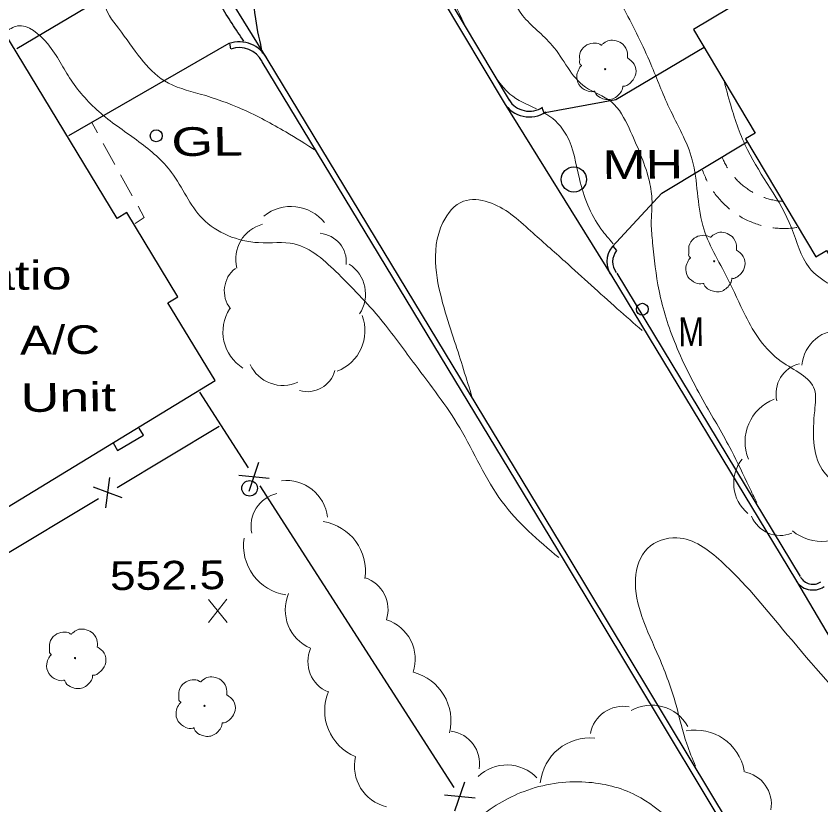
# Model space of a CAD drawing. Extents: x 2361708 to 2370558, y 6977955 to 6991887.
# Drawn here: x 2366412.5 to 2366547.1, y 6982751.7 to 6982883.6 of the extents above; entities that cross this region are included whole.
import ezdxf

# ---------------------------------------------------------------- set-up
doc = ezdxf.new("R2010")
doc.units = 0
doc.header["$LTSCALE"] = 1.9
for name, color, linetype, lineweight in [('11', 7, 'Continuous', 25), ('13', 7, 'Continuous', 13), ('14', 7, 'Continuous', 13), ('17', 7, 'Continuous', 25), ('2', 7, 'Continuous', 25), ('20', 7, 'Continuous', 25), ('23', 7, 'Continuous', 25), ('29', 7, 'Continuous', 13), ('31', 7, 'Continuous', 13), ('35', 7, 'Continuous', 13)]:
    doc.layers.add(name, color=color, linetype=linetype, lineweight=lineweight)

msp = doc.modelspace()

# ---------------------------------------------------------------- linework, layer by layer
at = {"layer": '11'}
for points in [[(2366556.942, 6982829.566), (2366598.547, 6982854.472), (2366579.524, 6982886.263), (2366569.301, 6982880.146), (2366557.3, 6982900.212), (2366525.798, 6982881.361), (2366536.143, 6982864.059), (2366534.502, 6982863.074), (2366546.301, 6982843.335), (2366548.061, 6982844.391)], [(2366404.142, 6982797.319), (2366445.793, 6982822.667), (2366437.889, 6982835.643), (2366439.559, 6982836.659), (2366430.994, 6982850.758), (2366429.374, 6982849.772), (2366410.435, 6982881.013), (2366381.789, 6982863.65), (2366388.231, 6982853.021), (2366387.068, 6982852.32), (2366391.914, 6982844.315), (2366393.087, 6982845.027), (2366403.114, 6982828.581), (2366389.96, 6982820.555)]]:
    msp.add_lwpolyline(points, close=True, dxfattribs=at)
at = {"layer": '13'}
for p, q in [((2366425.141, 6982865.822), (2366426.107, 6982864.072)), ((2366427.074, 6982862.321), (2366429.007, 6982858.819)), ((2366429.974, 6982857.068), (2366431.918, 6982853.567))]:
    msp.add_line(p, q, dxfattribs=at)
for points in [[(2366530.591, 6982860.026), (2366530.673, 6982859.837), (2366530.754, 6982859.648), (2366530.836, 6982859.459), (2366530.928, 6982859.269), (2366531.02, 6982859.08), (2366531.112, 6982858.901), (2366531.213, 6982858.722), (2366531.315, 6982858.543), (2366531.416, 6982858.364), (2366531.488, 6982858.244)], [(2366527.332, 6982857.825), (2366527.414, 6982857.586), (2366527.506, 6982857.357), (2366527.598, 6982857.118), (2366527.691, 6982856.888), (2366527.793, 6982856.649), (2366527.895, 6982856.42), (2366528.007, 6982856.201), (2366528.109, 6982855.982)], [(2366532.673, 6982856.636), (2366532.764, 6982856.537), (2366532.906, 6982856.378), (2366533.047, 6982856.229), (2366533.189, 6982856.081), (2366533.33, 6982855.942), (2366533.481, 6982855.794), (2366533.633, 6982855.655), (2366533.794, 6982855.516), (2366533.945, 6982855.387), (2366534.106, 6982855.249), (2366534.268, 6982855.121), (2366534.429, 6982854.992), (2366534.6, 6982854.874), (2366534.771, 6982854.756), (2366534.942, 6982854.637), (2366535.114, 6982854.519), (2366535.284, 6982854.41), (2366535.456, 6982854.302), (2366535.636, 6982854.194), (2366535.757, 6982854.125)], [(2366529.136, 6982854.272), (2366529.156, 6982854.242), (2366529.298, 6982854.043), (2366529.45, 6982853.835), (2366529.601, 6982853.636), (2366529.763, 6982853.438), (2366529.915, 6982853.249), (2366530.087, 6982853.061), (2366530.249, 6982852.872), (2366530.421, 6982852.684), (2366530.593, 6982852.496), (2366530.774, 6982852.318), (2366530.946, 6982852.139), (2366531.127, 6982851.971), (2366531.319, 6982851.803), (2366531.511, 6982851.634), (2366531.693, 6982851.466), (2366531.844, 6982851.348)], [(2366537.575, 6982853.292), (2366537.696, 6982853.253), (2366537.896, 6982853.185), (2366538.097, 6982853.117), (2366538.287, 6982853.059), (2366538.488, 6982853.011), (2366538.688, 6982852.953), (2366538.889, 6982852.904), (2366539.09, 6982852.857), (2366539.3, 6982852.819), (2366539.501, 6982852.78), (2366539.701, 6982852.742), (2366539.911, 6982852.715), (2366540.111, 6982852.686), (2366540.322, 6982852.668), (2366540.522, 6982852.64), (2366540.662, 6982852.632)], [(2366432.884, 6982851.816), (2366433.932, 6982849.936), (2366432.402, 6982848.901)], [(2366533.475, 6982850.193), (2366533.545, 6982850.154), (2366533.756, 6982850.026), (2366533.977, 6982849.898), (2366534.199, 6982849.78), (2366534.42, 6982849.662), (2366534.641, 6982849.554), (2366534.872, 6982849.446), (2366535.103, 6982849.339), (2366535.334, 6982849.241), (2366535.565, 6982849.143), (2366535.795, 6982849.055), (2366536.036, 6982848.957), (2366536.267, 6982848.88), (2366536.508, 6982848.802), (2366536.749, 6982848.724), (2366536.989, 6982848.647), (2366537.13, 6982848.618)], [(2366539.084, 6982848.216), (2366539.214, 6982848.197), (2366539.464, 6982848.17), (2366539.715, 6982848.142), (2366539.965, 6982848.125), (2366540.215, 6982848.107), (2366540.465, 6982848.099), (2366540.715, 6982848.092), (2366540.965, 6982848.094), (2366541.225, 6982848.097), (2366541.475, 6982848.099), (2366541.725, 6982848.111), (2366541.975, 6982848.124), (2366542.224, 6982848.146), (2366542.474, 6982848.169), (2366542.724, 6982848.201), (2366542.974, 6982848.233), (2366543.074, 6982848.244)]]:
    msp.add_lwpolyline(points, dxfattribs=at)
at = {"layer": '17'}
for p, q in [((2366443.161, 6982820.702), (2366451.281, 6982808.089)), ((2366429.371, 6982804.81), (2366446.455, 6982815.063)), ((2366451.469, 6982804.17), (2366453.103, 6982809.026)), ((2366427.484, 6982801.382), (2366428.166, 6982806.459)), ((2366449.733, 6982806.854), (2366454.828, 6982806.332)), ((2366430.228, 6982803.028), (2366425.431, 6982804.812)), ((2366453.23, 6982805.067), (2366485.722, 6982754.624)), ((2366374.841, 6982772.089), (2366426.289, 6982802.96)), ((2366485.909, 6982750.695), (2366487.543, 6982755.551)), ((2366484.173, 6982753.389), (2366489.269, 6982752.867))]:
    msp.add_line(p, q, dxfattribs=at)
at = {"layer": '2'}
for p, q in [((2366470.221, 6982909.064), (2366494.133, 6982869.089)), ((2366471.046, 6982909.552), (2366494.958, 6982869.577)), ((2366454.501, 6982876.433), (2366440.414, 6982899.14)), ((2366439.333, 6982894.049), (2366412.613, 6982878.124)), ((2366448.086, 6982879.012), (2366421.261, 6982863.596)), ((2366448.395, 6982878.105), (2366448.256, 6982879.053)), ((2366494.133, 6982869.089), (2366512.139, 6982840.13)), ((2366500.46, 6982868.32), (2366500.759, 6982867.412)), ((2366512.959, 6982844.407), (2366512.362, 6982845.162)), ((2366512.139, 6982840.13), (2366542.854, 6982789.379)), ((2366512.965, 6982840.627), (2366543.679, 6982789.877)), ((2366542.854, 6982789.379), (2366555.62, 6982767.83))]:
    msp.add_line(p, q, dxfattribs=at)
for points in [[(2366500.968, 6982867.504), (2366512.828, 6982869.637), (2366527.616, 6982878.389)], [(2366545.174, 6982726.348), (2366505.037, 6982793.03), (2366454.501, 6982876.433)], [(2366544.349, 6982725.851), (2366504.212, 6982792.532), (2366453.676, 6982875.935)], [(2366512.213, 6982845.01), (2366520.497, 6982854.02), (2366534.817, 6982862.576)]]:
    msp.add_lwpolyline(points, dxfattribs=at)
for centre, radius, start, end in [((2366449.8, 6982874.006), 5.291, 27.30467, 108.89451), ((2366449.8, 6982874.006), 4.331, 27.30467, 108.89451), ((2366498.344, 6982871.713), 4.002, 211.92522, 303.70783), ((2366498.344, 6982871.713), 4.962, 211.92522, 303.70783), ((2366515.252, 6982842.523), 3.927, 140.70792, 217.55996), ((2366515.252, 6982842.523), 2.967, 140.70792, 217.55996), ((2366545.798, 6982791.015), 3.368, 209.047, 303.46733), ((2366545.798, 6982791.015), 2.408, 209.047, 303.46733)]:
    msp.add_arc(centre, radius, start, end, dxfattribs=at)
at = {"layer": '20'}
for centre, radius in [((2366435.922, 6982863.595), 1), ((2366505.795, 6982856.29), 2.1), ((2366517.252, 6982834.578), 1)]:
    msp.add_circle(centre, radius, dxfattribs=at)
at = {"layer": '23'}
msp.add_line((2366428.721, 6982812.234), (2366429.453, 6982810.981), dxfattribs=at)
msp.add_lwpolyline([(2366429.453, 6982810.981), (2366433.799, 6982813.512), (2366433.087, 6982814.726)], dxfattribs=at)
msp.add_circle((2366451.544, 6982804.651), 1.3, dxfattribs=at)
at = {"layer": '29'}
for centre in [(2366511.03, 6982874.741), (2366529.277, 6982842.603), (2366422.343, 6982776.262), (2366443.99, 6982768.267)]:
    msp.add_circle(centre, 0.1, dxfattribs=at)
for centre, radius, start, end in [((2366458.467, 6982844.552), 7.214, 38.74011, 128.74011), ((2366455.231, 6982842.972), 6.015, 104.43417, 194.43417), ((2366462.915, 6982842.508), 4.807, 354.58077, 84.58077), ((2366452.122, 6982837.636), 4.807, 127.90568, 217.90568), ((2366464.918, 6982837.117), 6.015, 326.57837, 56.57837), ((2366454.302, 6982830.825), 7.214, 147.58499, 237.58499), ((2366463.629, 6982830.991), 7.214, 290.68721, 20.68721), ((2366550.382, 6982824.666), 6.456, 84.73193, 174.73193), ((2366457.107, 6982827.86), 6.015, 204.6795, 294.6795), ((2366544.775, 6982820.475), 5.159, 103.68714, 193.68714), ((2366461.187, 6982825.613), 4.807, 254.48101, 344.48101), ((2366542.175, 6982812.389), 7.744, 111.88068, 201.88068), ((2366538.99, 6982805.468), 6.456, 141.02643, 231.02643), ((2366457.672, 6982798.998), 6.954, 6.5904, 96.5904), ((2366457.337, 6982798.339), 5.557, 102.5934, 192.5934), ((2366540.324, 6982801.925), 5.159, 202.05062, 292.05062), ((2366462.583, 6982790.829), 8.34, 351.38122, 81.38122), ((2366547.251, 6982803.526), 7.744, 230.91842, 320.91842), ((2366458.878, 6982795.061), 8.34, 171.19948, 261.19948), ((2366469.159, 6982784.397), 5.557, 341.95264, 71.95264), ((2366464.47, 6982784.3), 6.954, 156.84818, 246.84818), ((2366472.303, 6982776.043), 6.954, 341.95264, 71.95264), ((2366466.859, 6982775.699), 5.557, 156.84818, 246.84818), ((2366476.882, 6982765.811), 8.34, 345.70719, 75.70719), ((2366472.447, 6982767.483), 8.34, 157.33632, 247.33632), ((2366518.798, 6982761.438), 6.954, 29.31445, 119.31445), ((2366514.026, 6982762.637), 5.557, 79.53142, 169.53142), ((2366484.479, 6982758.552), 5.557, 351.59786, 81.59786), ((2366526.104, 6982755.894), 8.34, 10.60009, 100.60009), ((2366508.481, 6982754.571), 8.34, 84.16288, 174.16288), ((2366476.043, 6982758.174), 6.954, 166.55582, 256.55582), ((2366494.596, 6982751.438), 6.954, 43.81111, 133.81111), ((2366533.285, 6982751.797), 5.557, 350.45668, 80.45668)]:
    msp.add_arc(centre, radius, start, end, dxfattribs=at)
for points in [[(2366507.064, 6982875.313), (2366507.084, 6982875.323), (2366507.003, 6982875.392), (2366506.767, 6982876.02), (2366506.805, 6982877.3), (2366507.693, 6982878.599), (2366508.998, 6982879.082), (2366510.12, 6982878.892), (2366510.352, 6982878.764), (2366510.422, 6982878.765), (2366510.472, 6982878.806), (2366510.818, 6982879.099), (2366511.684, 6982879.547), (2366512.895, 6982879.479), (2366514.011, 6982878.889), (2366514.744, 6982877.466), (2366514.752, 6982876.606)], [(2366514.742, 6982876.626), (2366515.882, 6982875.567), (2366516.167, 6982873.979), (2366515.46, 6982872.652), (2366514.805, 6982872.106), (2366514.137, 6982871.89), (2366513.987, 6982871.879), (2366513.968, 6982871.769), (2366513.647, 6982870.865), (2366512.108, 6982869.7), (2366510.215, 6982869.983), (2366509.316, 6982870.924), (2366509.244, 6982871.053), (2366509.125, 6982871.032), (2366507.914, 6982871.151), (2366506.644, 6982872.149), (2366506.299, 6982873.786), (2366506.669, 6982874.809), (2366506.995, 6982875.252), (2366507.064, 6982875.303)], [(2366525.311, 6982843.175), (2366525.331, 6982843.185), (2366525.25, 6982843.254), (2366525.014, 6982843.882), (2366525.052, 6982845.163), (2366525.94, 6982846.461), (2366527.245, 6982846.944), (2366528.367, 6982846.754), (2366528.598, 6982846.626), (2366528.668, 6982846.627), (2366528.718, 6982846.668), (2366529.065, 6982846.961), (2366529.931, 6982847.409), (2366531.141, 6982847.341), (2366532.257, 6982846.751), (2366532.991, 6982845.328), (2366532.999, 6982844.468)], [(2366532.989, 6982844.488), (2366534.129, 6982843.429), (2366534.414, 6982841.842), (2366533.707, 6982840.514), (2366533.052, 6982839.968), (2366532.384, 6982839.752), (2366532.234, 6982839.741), (2366532.215, 6982839.631), (2366531.894, 6982838.728), (2366530.355, 6982837.563), (2366528.462, 6982837.845), (2366527.563, 6982838.786), (2366527.492, 6982838.916), (2366527.372, 6982838.894), (2366526.161, 6982839.013), (2366524.891, 6982840.011), (2366524.546, 6982841.648), (2366524.916, 6982842.672), (2366525.242, 6982843.114), (2366525.311, 6982843.165)], [(2366418.377, 6982776.834), (2366418.397, 6982776.844), (2366418.317, 6982776.913), (2366418.081, 6982777.541), (2366418.118, 6982778.822), (2366419.006, 6982780.12), (2366420.311, 6982780.602), (2366421.433, 6982780.413), (2366421.664, 6982780.286), (2366421.734, 6982780.286), (2366421.784, 6982780.327), (2366422.131, 6982780.62), (2366422.997, 6982781.068), (2366424.208, 6982781), (2366425.323, 6982780.41), (2366426.057, 6982778.987), (2366426.066, 6982778.127)], [(2366426.055, 6982778.147), (2366427.195, 6982777.088), (2366427.48, 6982775.5), (2366426.773, 6982774.174), (2366426.118, 6982773.627), (2366425.45, 6982773.411), (2366425.3, 6982773.4), (2366425.281, 6982773.289), (2366424.96, 6982772.386), (2366423.421, 6982771.222), (2366421.528, 6982771.504), (2366420.629, 6982772.445), (2366420.558, 6982772.574), (2366420.438, 6982772.553), (2366419.227, 6982772.672), (2366417.958, 6982773.67), (2366417.612, 6982775.306), (2366417.982, 6982776.33), (2366418.308, 6982776.773), (2366418.377, 6982776.824)], [(2366440.024, 6982768.84), (2366440.044, 6982768.85), (2366439.964, 6982768.919), (2366439.728, 6982769.547), (2366439.765, 6982770.827), (2366440.653, 6982772.126), (2366441.959, 6982772.608), (2366443.081, 6982772.419), (2366443.312, 6982772.291), (2366443.381, 6982772.292), (2366443.431, 6982772.332), (2366443.778, 6982772.625), (2366444.644, 6982773.074), (2366445.855, 6982773.005), (2366446.971, 6982772.416), (2366447.705, 6982770.993), (2366447.713, 6982770.133)], [(2366447.702, 6982770.153), (2366448.842, 6982769.094), (2366449.127, 6982767.506), (2366448.42, 6982766.179), (2366447.765, 6982765.633), (2366447.097, 6982765.416), (2366446.948, 6982765.405), (2366446.929, 6982765.295), (2366446.607, 6982764.392), (2366445.068, 6982763.227), (2366443.175, 6982763.509), (2366442.276, 6982764.451), (2366442.205, 6982764.58), (2366442.086, 6982764.559), (2366440.874, 6982764.678), (2366439.605, 6982765.675), (2366439.259, 6982767.312), (2366439.629, 6982768.336), (2366439.955, 6982768.779), (2366440.024, 6982768.83)]]:
    msp.add_spline(points, degree=3, dxfattribs=at)
at = {"layer": '31'}
for p, q in [((2366447.777, 6982782.224), (2366444.661, 6982786.075)), ((2366444.697, 6982782.195), (2366447.74, 6982786.104))]:
    msp.add_line(p, q, dxfattribs=at)
at = {"layer": '31', "lineweight": 25}
for points in [[(2366461.379, 6982906.109), (2366459.625, 6982907.613), (2366452.046, 6982906.391), (2366450.728, 6982899.808), (2366451.725, 6982891.757), (2366452.517, 6982883.154), (2366453.672, 6982877.415)], [(2366450.603, 6982879.396), (2366446.745, 6982885.46), (2366443.575, 6982890.679), (2366440.963, 6982892.975), (2366439.603, 6982894.002)]]:
    msp.add_spline(points, degree=3, dxfattribs=at)
at = {"layer": '35'}
for points in [[(2366448.868, 6983015.416), (2366449.118, 6983014.368), (2366449.315, 6983006.229), (2366448.295, 6982998.939), (2366448.865, 6982994.725), (2366450.597, 6982990.271), (2366452.838, 6982983.902), (2366456.925, 6982976.91), (2366459.3, 6982966.943), (2366463.259, 6982958.6), (2366467.155, 6982952.757), (2366467.373, 6982946.689), (2366466.796, 6982942.173), (2366468.45, 6982936.498), (2366469.719, 6982934.47), (2366471.177, 6982933.664), (2366474.61, 6982928.097), (2366478.001, 6982923.829), (2366480.079, 6982918.828), (2366477.146, 6982913.87), (2366477.552, 6982903.773), (2366481.115, 6982896.137), (2366484.771, 6982888.101), (2366487.854, 6982881.5)], [(2366498.167, 6982978.923), (2366492.128, 6982974.596), (2366485.653, 6982964.603), (2366480.328, 6982955.642), (2366477.225, 6982949.642), (2366476.673, 6982944.607), (2366478.055, 6982938.18), (2366481.426, 6982932.781), (2366484.402, 6982926.93), (2366486.396, 6982920.208), (2366486.658, 6982913.691), (2366489.059, 6982906.303), (2366492.055, 6982896.211), (2366494.153, 6982890.111), (2366497.224, 6982883.719), (2366502.171, 6982878.717), (2366507.718, 6982871.749), (2366512.082, 6982869.25), (2366515.034, 6982864.858), (2366516.915, 6982860.536), (2366518.335, 6982856.349), (2366518.857, 6982853.064), (2366518.746, 6982848.873), (2366518.977, 6982845.715), (2366520.053, 6982837.675), (2366522.829, 6982828.671), (2366527.722, 6982818.847), (2366532.158, 6982810.949), (2366535.116, 6982804.906), (2366536.401, 6982802.259)], [(2366487.479, 6982945.12), (2366487.459, 6982945.03), (2366489.409, 6982940.938), (2366492.967, 6982933.771), (2366496.608, 6982928.516), (2366502.105, 6982921.378), (2366502.824, 6982915.265), (2366503.691, 6982908.232), (2366507.502, 6982900.699), (2366509.644, 6982894.258), (2366514.245, 6982884.672), (2366518.673, 6982875.563), (2366521.752, 6982868.262), (2366525.605, 6982859.548), (2366527.359, 6982848.615), (2366531.524, 6982839.734), (2366534.504, 6982833.512), (2366540.497, 6982825.859), (2366546.051, 6982821.181), (2366546.086, 6982817.601), (2366547.349, 6982807.793), (2366553.124, 6982802.068), (2366556.803, 6982795.882), (2366561.19, 6982790.944), (2366564.926, 6982782.929), (2366566.494, 6982775.794), (2366568.898, 6982768.036), (2366571.003, 6982760.186), (2366572.832, 6982752.933), (2366574.281, 6982747.797), (2366575.894, 6982742.242), (2366578.499, 6982734.426), (2366582.005, 6982725.319)], [(2366462.728, 6982861.08), (2366457.587, 6982864.241), (2366450.401, 6982868.003), (2366443.286, 6982870.576), (2366437.305, 6982872.769), (2366433.379, 6982876.482), (2366429.59, 6982881.596), (2366427.321, 6982885.714), (2366430.033, 6982890.78), (2366433.227, 6982895.631), (2366431.478, 6982899.795), (2366425.608, 6982903.919), (2366419.733, 6982908.623), (2366414.329, 6982913.222), (2366408.184, 6982920.014), (2366403.25, 6982926.757), (2366400.114, 6982929.348), (2366396.274, 6982930.451)], [(2366503.267, 6982793.063), (2366493.778, 6982802.403), (2366486.71, 6982814.746), (2366479.239, 6982825.325), (2366473.962, 6982832.325), (2366466.403, 6982840.484), (2366459.026, 6982845.504), (2366453.053, 6982845.727), (2366443.664, 6982849.758), (2366438.481, 6982857.459), (2366433.032, 6982862.608), (2366426.686, 6982867.317), (2366421.673, 6982872.92), (2366417.765, 6982878.953), (2366412.707, 6982881.955), (2366410.596, 6982880.925)], [(2366491.238, 6982875.872), (2366495.099, 6982870.579), (2366499.552, 6982868.111)], [(2366530.826, 6982873.099), (2366532.039, 6982868.69), (2366534.85, 6982861.236), (2366542.214, 6982848.186), (2366545.147, 6982841.574), (2366552.718, 6982836.205), (2366552.97, 6982836.018)], [(2366500.779, 6982867.433), (2366501.261, 6982867.167), (2366504.565, 6982863.689), (2366506.714, 6982856.409), (2366510.334, 6982848.022), (2366512.378, 6982845.542)], [(2366382.922, 6982861.251), (2366380.257, 6982859.665), (2366372.65, 6982850.962), (2366370.566, 6982842.942), (2366371.881, 6982836.064), (2366373.934, 6982830.524), (2366377.527, 6982823.937), (2366379.318, 6982818.584), (2366382.534, 6982807.454), (2366387.31, 6982798.429), (2366394.727, 6982792.56), (2366398.95, 6982784.829), (2366403.53, 6982777.573), (2366405.778, 6982770.374), (2366406.928, 6982765.104), (2366408.444, 6982755.039), (2366408.701, 6982742.78), (2366411.114, 6982732.943), (2366415.493, 6982726.804), (2366422.364, 6982720.449), (2366422.656, 6982720.212), (2366426.278, 6982715.866), (2366426.706, 6982711.92), (2366427.041, 6982705.043), (2366429.311, 6982696.634), (2366432.824, 6982691.097), (2366438.218, 6982683.368), (2366438.706, 6982678.313), (2366435.554, 6982671.082), (2366435.6, 6982661.102), (2366432.179, 6982653.849), (2366430.358, 6982642.291), (2366431.939, 6982633.876), (2366432.428, 6982628.67), (2366427.3, 6982625.252), (2366422.187, 6982620.303), (2366411.011, 6982613.596), (2366401.31, 6982608.413), (2366389.859, 6982599.974), (2366377.935, 6982590.85), (2366368.381, 6982582.889), (2366358.008, 6982576.92), (2366350.914, 6982573.012), (2366345.686, 6982567.552), (2366342.308, 6982559.96), (2366345.313, 6982553.118), (2366349.203, 6982544.754), (2366352.385, 6982539.344), (2366355.804, 6982530.987), (2366360.814, 6982523.714), (2366365.289, 6982515.836), (2366371.123, 6982510.161), (2366377.259, 6982508.57), (2366380.741, 6982509.363), (2366382.407, 6982506.708), (2366384.016, 6982502.584), (2366382.344, 6982498.537), (2366381.598, 6982495.02), (2366382.985, 6982492.163), (2366387.012, 6982490.461), (2366388.886, 6982485.779), (2366391.028, 6982481.449), (2366393.832, 6982476.806), (2366393.153, 6982474.609), (2366390.976, 6982472.219), (2366392.011, 6982466.338), (2366394.788, 6982461.484), (2366398.613, 6982454.61), (2366401.47, 6982448.717), (2366403.744, 6982443.038), (2366409.672, 6982439.115), (2366413.643, 6982435.792), (2366415.717, 6982432.212), (2366416.675, 6982430.351)], [(2366517.226, 6982831.037), (2366513.061, 6982834.678), (2366504.336, 6982842.546), (2366498.557, 6982847.691), (2366491.48, 6982852.513), (2366487.329, 6982852.654), (2366483.883, 6982849.081), (2366482.714, 6982841.58), (2366484.079, 6982834.832), (2366485.852, 6982829.199), (2366488.802, 6982819.817)], [(2366561.758, 6982757.548), (2366553.715, 6982766.232), (2366540.722, 6982781.109), (2366530.434, 6982792.441), (2366523.046, 6982796.371), (2366518.103, 6982794.604), (2366516.111, 6982789.505), (2366517.172, 6982783.215), (2366520.057, 6982776.332), (2366522.902, 6982768.398), (2366524.674, 6982761.925), (2366526.16, 6982758.199)], [(2366538.276, 6982735.533), (2366531.549, 6982740.47), (2366521.976, 6982749.149), (2366516.226, 6982753.304), (2366507.765, 6982755.524), (2366497.469, 6982753.976), (2366489.493, 6982749.28), (2366486.17, 6982746.397), (2366473.521, 6982737.857), (2366463.429, 6982732.791), (2366454.063, 6982727.031), (2366447.976, 6982723.543), (2366442.243, 6982719.649), (2366439.87, 6982711.535), (2366440.339, 6982707.38)]]:
    msp.add_spline(points, degree=3, dxfattribs=at)

# ---------------------------------------------------------------- texts
at = {"layer": '14', "width": 1.4}
msp.add_text('Patio', height=4.8, rotation=0.545, dxfattribs=at).set_placement((2366401.297, 6982837.735))
at = {"layer": '20'}
for s, width, p in [('  GL', 1.4, (2366433.485, 6982860.142)), ('  MH', 1.35, (2366505.795, 6982856.29)), ('M', 0.8, (2366523.311, 6982828.405)), ('A/C', 1.25, (2366413.159, 6982827.007)), ('Unit', 1.4, (2366413.251, 6982817.407))]:
    msp.add_text(s, height=4.8, rotation=0.545, dxfattribs=dict(at, width=width)).set_placement(p)
at = {"layer": '31', "width": 1.2}
msp.add_text('552.5', height=4.8, rotation=0.545, dxfattribs=at).set_placement((2366428.205, 6982787.618))

doc.saveas('drawing.dxf')
